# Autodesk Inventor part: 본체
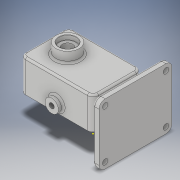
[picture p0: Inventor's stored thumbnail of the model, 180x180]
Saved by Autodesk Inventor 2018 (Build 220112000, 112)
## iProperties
Created: 2020-04
Part Number: 본체
Material: Generic
Document SubType Name: Modeling
Designer: 1class 18
Density: 1 g/cm^3
Appearance: Default
Author: 1class 18
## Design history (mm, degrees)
node "주석"
  node "선형 치수 1" dims "d100" = 62 (derived)
sketch "스케치1"
  geometry: 1 further point
sketch "스케치2"
  geometry: L1 (0, 0)-(120, 0); L2 (120, 0)-(120, -80); L3 (120, -80)-(0, -80); L4 (0, -80)-(0, 0); L5 (82, -16)-(38, -16); L6 (38, -64)-(82, -64); A1 r 24 centre (82, -40) between (82, -64) and (82, -16); A2 r 24 centre (38, -40) between (38, -16) and (38, -64)
  constraints: 12 end point, 4 point on circle, 3 parallel, 2 centre point, 2 horizontal, 2 tangent, 1 perpendicular
  dimensions: "d0" = 120 distance of L2.end L3.end; "d1" = 80 distance of L1.end L2.end; "d2" = 48 diameter of A1; "d3" = 48 diameter of A2; "d4" = 44 distance of A2.centre A1.centre; "d5" = 40 distance from line of L1 A1.centre; "d6" = 38 distance from line of L2 A1.centre
extrude "돌출1" new body sketch "스케치2" distance "d7" = 53; taper "d8" = 0 deg
sketch "스케치3"
  geometry: L1 (-120, 0)-(0, 0) reference; L2 (-120, 80)-(-120, 0) reference; C1 r 12.5 at (-82, 40); C2 r 12.5 at (-38, 40)
  constraints: 2 centre point, 1 horizontal alignment
  dimensions: "d9" = 25 diameter of C1; "d10" = 25 diameter of C2; "d11" = 40 distance from line of L1 C1.centre; "d12" = 38 distance from line of L2 C1.centre; "d13" = 44 distance of C1.centre C2.centre
extrude "돌출2" join sketch "스케치2" distance "d14" = 53; taper "d15" = 0 deg
extrude "돌출3" cut sketch "스케치2" distance "d16" = 29; taper "d17" = 0 deg
sketch "스케치4"
  geometry: L1 (-120, 0)-(-120, -80) reference; L2 (-120, -80)-(0, -80) reference; C1 r 12.5 at (-38, -40); C2 r 12.5 at (-82, -40); 1 further point
  constraints: 2 centre point, 1 horizontal alignment
  dimensions: "d18" = 25 diameter of C1; "d19" = 25 diameter of C2; "d20" = 38 distance from line of L1 C2.centre; "d21" = 40 distance from line of L2 C2.centre; "d22" = 44 distance of C2.centre C1.centre
extrude "돌출4" cut sketch "스케치4" distance "d23" = 15; taper "d24" = 0 deg
sketch "스케치5"
  geometry: C1 r 12.5 at (-82, 40) reference; C2 r 19 at (-82, 40); 1 further point
  constraints: 1 centre point, 1 coincident
  dimensions: "d25" = 38 diameter of C2
extrude "돌출5" join sketch "스케치5" distance "d26" = 17; taper "d27" = 0 deg
sketch "스케치6"
  geometry: C1 r 14 at (0, 0); 1 further point
  constraints: 1 centre point
  dimensions: "d28" = 28 diameter of C1
extrude "돌출6" cut sketch "스케치6" distance "d29" = 7.3; taper "d30" = 0 deg
sketch "스케치7"
  geometry: C1 r 8.5 at (0, 0); 1 further point
  constraints: 1 centre point
  dimensions: "d31" = 17 diameter of C1
extrude "돌출7" cut sketch "스케치7" extent not by distance; stored distance "d32" = 7.3; taper "d33" = 0 deg
node "작업 평면1"
sketch "스케치8"
  geometry: L1 (-30, -100)-(70, -100); L2 (70, -100)-(70, 20); L3 (70, 20)-(-30, 20); L4 (-30, 20)-(-30, -100); L5 (70, -59)-(70, -21) reference; L6 (0, -80)-(53, -80) reference; 1 further point
  constraints: 8 end point, 2 parallel, 1 horizontal, 1 perpendicular
  dimensions: "d35" = 100 distance of L3.end L2.end; "d36" = 120 distance of L2.end L1.end; "d37" = 0 distance between parallel lines of L5 L2; "d38" = 20 distance between parallel lines of L6 L1
extrude "돌출8" join sketch "스케치8" distance "d39" = 10; taper "d40" = 0 deg
node "작업 평면2"
sketch "스케치9"
  geometry: L1 (20, 70)-(20, -30) reference; L2 (0, 0)-(-120, 0) reference; L3 (0, 0)-(0, 53) reference; L4 (-120, 53)-(0, 53) reference; L5 (30, 70)-(30, -30) reference; L6 (20, -30)-(20, 70) reference; L7 (30, 70)-(20, 70) reference; L8 (20, 0)-(-3.153, 13.367); L9 (0, 0)-(0, 53) reference; L10 (20, 0)-(43.094, 0); L11 (20, 53)-(-3.153, 39.633); L12 (20, 53)-(48.512, 53); L13 (-3.153, 39.633)-(-3.153, 13.367); L14 (20, 0)-(20, 53)
  constraints: 12 end point, 2 horizontal, 2 point on line, 1 collinear, 1 vertical
  dimensions: "d42" = 17 distance from line of L7 L11.start; "d43" = 53 distance of L8.start L11.start; "d44" = 150 deg angle of L10 L8; "d45" = 150 deg angle of L11 L12
extrude "돌출9" join sketch "스케치9" stored distance "d46" = 48; taper "d47" = 0 deg
sketch "스케치10"
  geometry: L1 (-120, -80)-(0, -80) reference; L2 (-120, 0)-(-120, -80) reference; L3 (-120, -40)-(0, -40); L4 (0, 0)-(0, -80) reference; 8 further points
  constraints: 4 symmetric about line, 3 horizontal alignment, 2 end point, 2 midpoint
  dimensions: "d48" = 9 distance from line of L1 point (-111, -71); "d49" = 9 distance from line of L2 point (-111, -71); "d50" = 29 distance of point (-111, -71) point (-82, -71); "d51" = 44 distance of point (-38, -71) point (-82, -71); "d52" = 29 distance of point (-38, -71) point (-9, -71)
hole "구멍1" sketch "스케치10" at (-111, -71), (-82, -71), (-38, -71), (-9, -71), (-9, -9), (-38, -9), (-82, -9), (-111, -9) diameter "d53" = 4.134; stored, may be unused: countersink angle "d57" = 90 deg, drill point angle "d59" = 118 deg; dims "d54" = 10, "d55" = 4, "d56" = 2, "d58" = 12
sketch "스케치11"
  geometry: L1 (120, 0)-(0, 0) reference; L2 (120, 0)-(120, 53) reference; C1 r 11 at (60, 14)
  constraints: 1 centre point
  dimensions: "d60" = 22 diameter of C1; "d61" = 14 distance from line of L1 C1.centre; "d62" = 60 distance from line of L2 C1.centre
extrude "돌출10" join sketch "스케치11" distance "d63" = 8; taper "d64" = 0 deg
sketch "스케치12"
  geometry: 2 further points
hole "구멍2" sketch "스케치12" at (0, 0) diameter "d65" = 8.376; stored, may be unused: countersink angle "d69" = 90 deg, drill point angle "d71" = 118 deg; dims "d66" = 27, "d67" = 4, "d68" = 2, "d70" = 27.3
node "작업 평면3"
fillet "모깎기1" dims "d73" = 3
fillet "모깎기2" dims "d74" = 3
sketch "스케치13"
  geometry: L1 (20, 70)-(-100, 70) reference; L2 (-100, 70)-(-100, -30) reference; L3 (-40, 70)-(-40, -30); L4 (-100, -30)-(20, -30) reference; L5 (-100, 20)-(20, 20); C1 r 4.5 at (-90, 60); C2 r 4.5 at (-90, -20); C3 r 4.5 at (10, 60); C4 r 4.5 at (10, -20); 1 further point
  constraints: 4 centre point, 4 end point, 3 midpoint, 3 symmetric about line, 1 horizontal, 3 other
  dimensions: "d75" = 9 diameter of C1; "d76" = 10 distance from line of L1 C1.centre; "d77" = 10 distance from line of L2 C1.centre
extrude "돌출11" cut sketch "스케치13" distance "d78" = 10; taper "d79" = 0 deg
sketch "스케치14"
  geometry: L1 (-100, 70)-(-100, -30) reference; L2 (-100, -30)-(20, -30) reference; 2 further points
  constraints: 1 other
  dimensions: "d80" = 60 distance from line of L1 point (-40, -20); "d81" = 10 distance from line of L2 point (-40, -20)
extrude "돌출12" join sketch "스케치14" distance "d82" = 0.5; taper "d83" = 0 deg
fillet "모깎기3" dims "d84" = 10
fillet "모깎기4" dims "d85" = 3
fillet "모깎기5" dims "d86" = 9
fillet "모깎기6" dims "d87" = 3
fillet "모깎기7" dims "d88" = 3
chamfer "모따기1" distance "d89" = 0.7; stored, may be unused: second distance "d90" = 2, angle "d91" = 30 deg
fillet "모깎기8" dims "d92" = 0.5
chamfer "모따기2" distance "d93" = 1; stored, may be unused: second distance "d94" = 2, angle "d95" = 30 deg
fillet "모깎기9" dims "d96" = 3
fillet "모깎기10" dims "d97" = 3
node "솔리드1"
mirror "미러1"
other parameters: "d98" = 6.49151 (derived), "d99" = 4.54171 (derived)
